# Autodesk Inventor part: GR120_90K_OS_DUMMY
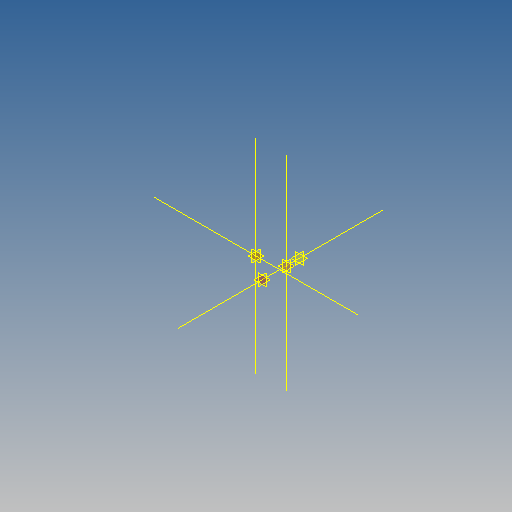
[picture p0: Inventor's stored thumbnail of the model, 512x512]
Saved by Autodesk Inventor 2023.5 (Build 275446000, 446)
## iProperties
Part Number: GR120_90K_OS_DUMMY
Material: Allgemein
Document SubType Name: Modellieren
Designer: WH
Appearance: Vorgabe
Author: WH
NB: GR120-90K-OS_dummy
NN: GR120-OS
NBSYN: $CNSORDERNO._dummy
LINA: GR120-90K-OS_dummy
CATALOG: GIGAGER
CNSORDERNO: GR120-90K-OS
SCS: GR120
GR: 90K
MS: OS
SUPPLIER: SAINI
ARTICLENO: GR120-90K-OS_dummy
BOMINFO: GR120-90K-OS_dummy
CREATOR: CADENAS GmbH
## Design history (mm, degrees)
node "A_1"
node "1_ZAXS"
node "2_ZAXS"
node "3_ZAXS"
node "4_ZAXS"
node "RIGHT"
node "TOP"
node "FRONT"
node "1_XPLN"
node "1_YPLN"
node "1_ZPLN"
node "2_XPLN"
node "2_YPLN"
node "2_ZPLN"
node "3_XPLN"
node "3_YPLN"
node "3_ZPLN"
node "4_XPLN"
node "4_YPLN"
node "4_ZPLN"
node "Volumenkörper"
node "Flächenkörper"
